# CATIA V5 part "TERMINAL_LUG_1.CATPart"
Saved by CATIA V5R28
Part number: TERMINAL_LUG_1
Revision: --A
Publications: "Logical Termination.1", "Logical Pin.1", "BCP", "BCPRPoint_generated(BCP)", "BCPPlane_generated(BCP)", "CaCP", "Face_generated(CaCP)", "Axis_generated(CaCP)", "Face_generated(CaCP).1"
Bounding box of the stored display mesh (mm): x -3.486 to 15.519, y -3.562 to 3.562, z -0.885 to 4.187
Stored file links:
  C:\Users\ajc8720\Documents\BOEING_WORK\0001-2CES\004-AP242\Boeing-Generic_Harness_R3\TERMINAL_LUG_1.CATPart
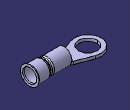
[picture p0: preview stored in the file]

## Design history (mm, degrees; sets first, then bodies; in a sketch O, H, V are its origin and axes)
Parameters
  PartNumber = "TERMINAL_LUG_1"
Set1
  Plane1: type Offset, RefPlane yz-plane, Offset 6.35 {= deleted_LENGTH}
  Sketch1 on Plane1, origin (6.35, 0, 0), H (0, 1, 0), V (0, 0, 1)
    point P1 (-1.6479, 1.5494)
    point P2 (1.6479, 1.5494)
    reference projected circle E1 centre (0, 1.651) radius 1.651 from edge [face of Pad1 from Sketch2.A1 | end face of Pad1]
    reference projected circle E2 centre (0, 1.651) radius 1.651 from edge [face of Pad1 from Sketch2.A1 | end face of Pad1]
    arc A1 centre (0, 1.651) radius 1.651 from (1.6479, 1.5494) to (0, 0) cw
    arc A2 centre (0, 1.651) radius 1.651 from (0, 0) to (-1.6479, 1.5494) cw
    line L1 (-1.6479, 1.5494) -> (1.6479, 1.5494)
    point P5 (-1.6479, 1.5494)
    point P6 (1.6479, 1.5494)
    reference intersected line E3 through (0, 0) direction (-1, 0) from xy-plane
    reference projected circle E4 centre (0, 1.651) radius 1.651 from edge [start face of Pad1 | face of Pad1 from Sketch2.A1]
    reference projected circle E5 centre (0, 1.651) radius 1.651 from edge [start face of Pad1 | face of Pad1 from Sketch2.A1]
    distance L1 E3 = 1.5494 {= deleted_LENGTH + .03in}
    coincidence: P2 E1, P1 E2, A1 E4, A2 E5, P1 P5, P6 P2
    horizontal: L1 H
Set2 "EGF"
  Set3 "BCP"
    Plane2 "BCPPlane": type OffsetPt, RefPlane face of Shaft1 from Sketch5.L17, RefPoint Point1
    Point1 "BCPRPoint": type Center, Curve edge [face of Shaft1 from Sketch5.L17 | face of Shaft1 from Sketch5.A5]
  Set4 "CaCP"
    Plane3 "CaCPCPlane": type Offset, RefPlane xy-plane, Offset 0
    Point2 "CaCPRPoint": type Center, Curve edge [face of Pad2 from Sketch3.A2 | face of Pad2]
Body1 "Body" (main body)
  Sketch2 on Plane1, origin (6.35, 0, 0), H (0, 1, 0), V (0, 0, 1)
    point P1 (0, 1.651)
    circle A1 centre (0, 1.651) radius 1.651
    reference intersected line E1 through (0, 0) direction (0, 1) from zx-plane
    reference intersected line E2 through (0, 0) direction (-1, 0) from xy-plane
    radius A1 = 1.651
    coincidence: P1 E1
    tangency: A1 E2
  Pad1: profile Sketch2, direction (1, 0, 0), length 4.5847 {= .5*(deleted_LENGTH-deleted_LENGTH)}
  Sketch3 on xy-plane, origin (0, 0, 0), H (1, 0, 0), V (0, 1, 0)
    arc A1 centre (0, 0) radius 3.5687 from (1.2968, 3.3247) to (1.2968, -3.3247) ccw
    line L1 (1.2968, 3.3247) -> (5.588, 1.651)
    line L2 (5.588, 1.651) -> (5.588, -1.651)
    line L3 (5.588, -1.651) -> (1.2968, -3.3247)
    reference intersected line E1 through (0, 0) direction (-1, 0) from zx-plane
    reference intersected line E2 through (0, 0) direction (0, 1) from yz-plane
    circle A2 centre (0, 0) radius 2.5019
    radius A1 = 3.5687
    distance L2 E2 = 5.588
    radius A2 = 2.5019
    length L2 = 3.302
    vertical: L2 V
    tangency: L3 A1, L1 A1
    symmetry: L1 L3 E1
  Pad2: profile Sketch3, direction (0, 0, 1), length 0.7874 {= deleted_LENGTH}
  Loft1: solid, Sections (Boundary1; Sketch1), SectionCouplingPoints ({coupling CouplingPoints (vertex [face of Pad2 from Sketch3.L2 | end face of Pad2 | face of Pad2 from Sketch3.L3]; vertex [element of Sketch1 | element of Sketch1])}; {coupling CouplingPoints ({point type OnCurve, Support edge [face of Pad2 from Sketch3.L2 | end face of Pad2], Ratio 0}; vertex [element of Sketch1 | element of Sketch1])}; {coupling CouplingPoints (vertex [face of Pad2 from Sketch3.L1 | start face of Pad2 | face of Pad2 from Sketch3.L2]; Sketch1.O)}; {coupling CouplingPoints (vertex [face of Pad2 from Sketch3.L2 | start face of Pad2 | face of Pad2 from Sketch3.L3]; Sketch1.O)}), StartFace face of Pad2 from Sketch3.L2
  Sketch4 on end face of Pad1, origin (10.9347, 0, 1.651), H (0, 1, 0), V (0, 0, 1)
    point P1 (0, 0)
    reference intersected line E1 through (0, 0) direction (0, 1) from zx-plane
    reference intersected line E2 through (0, -1.651) direction (-1, 0) from xy-plane
    distance P1 E2 = 1.651
    coincidence: P1 E1
  Hole1: placed by Sketch4, at (10.9347, 0, 1.651) direction (-1, 0, 0), diameter 1.7272 {= deleted_LENGTH}, depth 15.5194 {= deleted_LENGTH}
  Boundary1: Boundary Extract1
  Extract1: ExtractElem face of Pad2 from Sketch3.L2
Body2 "Sleeve"
  Sketch5 on zx-plane, origin (0, 0, 0), H (0, 0, 1), V (1, 0, 0)
    line L1 (-0.4445, 6.35) -> (-0.4445, 10.9347)
    line L2 (-0.292, 11.3029) -> (-0.0942, 11.5007)
    line L3 (-0.0942, 11.6085) -> (-0.4825, 11.9968)
    line L4 (-0.635, 12.365) -> (-0.635, 15.1614)
    arc A1 centre (-1.016, 15.1614) radius 0.381 from (-0.635, 15.1614) to (-0.8857, 15.5194) ccw
    point P3 (-1.016, 15.1614)
    line L5 (-0.4445, 6.35) -> (0, 6.35)
    point P5 (0, 6.35)
    reference intersected line E1 (3.302, 6.35) -> (0, 6.35) from start face of Pad1
    reference intersected line E2 through (0, 0) direction (0, 1) from face of Pad2
    arc A2 centre (-0.148, 11.5546) radius 0.0762 from (-0.0942, 11.6085) to (-0.0942, 11.5007) cw
    arc A3 centre (0.0762, 10.9347) radius 0.5207 from (-0.292, 11.3029) to (-0.4445, 10.9347) ccw
    point P10 (-0.4445, 10.9347)
    arc A4 centre (-0.1143, 12.365) radius 0.5207 from (-0.4825, 11.9968) to (-0.635, 12.365) cw
    reference intersected line E3 (0, 10.9347) -> (3.302, 10.9347) from end face of Pad1
    line L6 (0, 6.35) -> (0, 10.9347)
    point P15 (0, 10.9347)
    line L7 (0.2202, 11.9228) -> (-0.1682, 12.3111)
    line L8 (-0.1905, 12.365) -> (-0.1905, 15.1614)
    arc A5 centre (-1.016, 15.1614) radius 0.8255 from (-0.1905, 15.1614) to (-0.2722, 15.5194) ccw
    point P17 (-1.016, 15.1614)
    construction line L9 (-0.1905, 15.1614) -> (-0.635, 15.1614)
    arc A6 centre (-0.1143, 12.365) radius 0.0762 from (-0.1905, 12.365) to (-0.1682, 12.3111) ccw
    construction line L10 (-0.1905, 12.365) -> (-0.635, 12.365)
    construction line L11 (-0.1682, 12.3111) -> (-0.4825, 11.9968)
    construction line L12 (0.2202, 11.9228) -> (-0.0942, 11.6085)
    reference intersected line E4 (0, 10.9347) -> (3.302, 10.9347) from end face of Pad1
    arc A7 centre (0.0762, 10.9347) radius 0.0762 from (0, 10.9347) to (0.0223, 10.9886) cw
    line L13 (0.0223, 10.9886) -> (0.2202, 11.1864)
    arc A8 centre (-0.148, 11.5546) radius 0.5207 from (0.2202, 11.1864) to (0.2202, 11.9228) ccw
    construction line L14 (-0.292, 11.3029) -> (0.0223, 10.9886)
    construction line L15 (-0.0942, 11.5007) -> (0.2202, 11.1864)
    axis line L16 (1.651, 35.9212) -> (1.651, 6.35)
    point P27 (1.651, 6.35)
    line L17 (-0.8857, 15.5194) -> (-0.2722, 15.5194)
    construction line L18 (-1.016, 15.1614) -> (-0.8857, 15.5194)
    reference intersected line E5 through (0, 0) direction (-1, 0) from yz-plane
    angle L2 L1 = 135
    radius A2 = 0.0762
    radius A1 = 0.381
    radius A6 = 0.0762
    radius A7 = 0.0762
    distance L16 L6 = 1.651
    radius about axis L8 L16 = 1.8415
    distance A8 L6 = 0.3727
    angle L18 L9 = 70
    radius about axis L1 L16 = 2.0955
    distance L17 E5 = 15.5194
    vertical: L1 V, L4 V, L6 V, L8 V, L16 V
    perpendicularity: L3 L2, L11 L7, L12 L7, L14 L2, L15 L2
    tangency: A1 L4, A2 L3, A2 L2, A3 L2, A3 L1, A4 L3, A4 L4, A5 L8, A6 L8, A6 L7, A7 L6, L13 A7, A8 L13, A8 L7
    horizontal: L5 H, L9 H, L10 H, L17 H
    coincidence: L5 E1, P5 E2, P10 E3, P15 E4, P27 L5, P17 P3
    parallelism: L7 L3, L13 L2
  Shaft1: profile Sketch5, axis axis of face of Pad1 from Sketch2.A1, angle 360
Body3 "CaCP"
  Sketch6 "Sketch" on Plane3, origin (0, 0, 0), H (0, 1, 0), V (-1, 0, 0)
    line L1 (-0.672, 0.762) -> (0.672, 0.762)
    point P1 (-0.672, 0.762)
    point P2 (0.672, 0.762)
    arc A1 centre (0, 0) radius 1.016 from (-1.016, 0) to (1.016, 0) ccw
    point P3 (0, 0)
    point P4 (-1.016, 0)
    point P5 (1.016, 0)
    reference projected point E1 (0, 0) from Point2
    arc A2 centre (0, 0) radius 1.016 from (1.016, 0) to (0.672, 0.762) ccw
    point P6 (0, 0)
    point P7 (1.016, 0)
    point P8 (0.672, 0.762)
    arc A3 centre (0, 0) radius 1.016 from (-0.672, 0.762) to (-1.016, 0) ccw
    point P9 (0, 0)
    point P10 (-0.672, 0.762)
    point P11 (-1.016, 0)
    reference projected point E2 (0, 0) from Point2
    reference projected point E3 (0, 0) from Point2
    length L1 = 1.344
    radius A1 = 1.016
    radius A3 = 1.016
    radius A2 = 1.016
    distance L1 P5 = 0.762
    distance P4 L1 = 0.762
    distance P7 L1 = 0.762
    distance P11 L1 = 0.762
    coincidence: P3 E1, P6 E2, P9 E3, P8 P2, P10 P1
    horizontal: L1 H
  Pad3: profile Sketch6, direction (0, 0, 1), length 0.508, opposite side up to Plane3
